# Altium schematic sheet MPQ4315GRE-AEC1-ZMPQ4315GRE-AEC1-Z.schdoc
size 127 x 101 mm
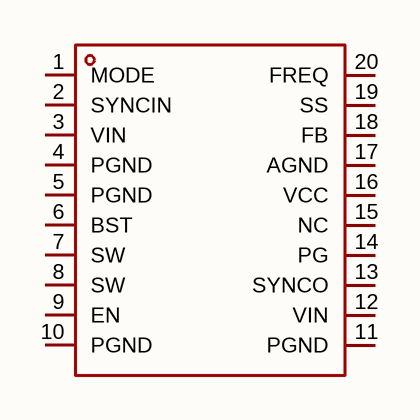
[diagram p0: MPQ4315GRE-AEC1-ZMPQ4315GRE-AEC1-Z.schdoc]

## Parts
U?  mpq4315gre-aec1-z  [QFN-20_L4.0-W4.0_MP4316GRE-Z]  (value not drawn)

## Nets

Not connected (* = marked no-connect by the designer): U? 1(MODE) 2(SYNCIN) 3(VIN) 4(PGND) 5(PGND) 6(BST) 7(SW) 8(SW) 9(EN) 10(PGND) 11(PGND) 12(VIN) 13(SYNCO) 14(PG) 15(NC) 16(VCC) 17(AGND) 18(FB) 19(SS) 20(FREQ)

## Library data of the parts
U? = mpq4315gre-aec1-z: 功能类型:降压型;工作电压:3.3V~45V;输出电压:815mV~42.75V;输出电流:5A;输出类型:可调;; Manufacturer: MPS(芯源); AddInBom: yes; ModelId: 3633c5b6617f4081b99ae2cf2dcc1425; ModelTransform: 157.559,157.559,0,0,0,0,0,0,0; Function: 降压型; Output Current: 5A; Frequency - Switching: 350kHz~1MHz; Synchronous Rectifier: 是; Number of Outputs: 1; Topology: 降压式; Quiescent Current: 18uA; Switch tube (built-in/external): 内置; Output Type: 可调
